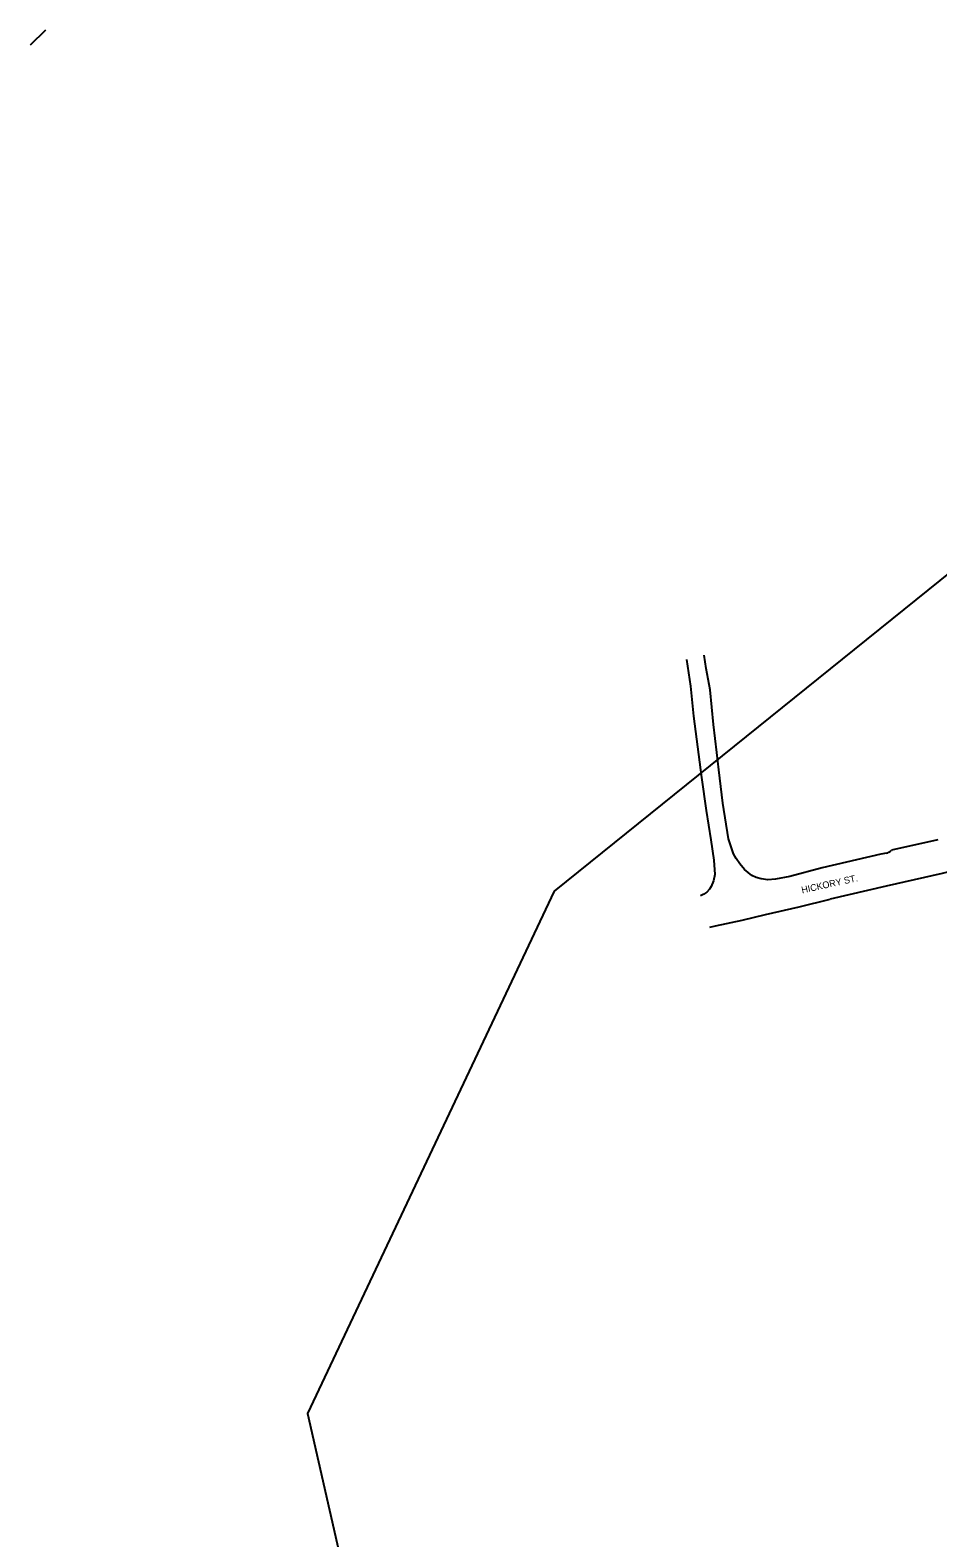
# Model space of a CAD drawing. Extents: x 553958 to 562499, y 493978 to 516388.
# Drawn here: x 556735 to 557275, y 506244 to 507140 of the extents above; entities that cross this region are included whole.
import ezdxf

# ---------------------------------------------------------------- set-up
doc = ezdxf.new("R2010")
doc.units = 0
for name, color, linetype in [('Prop Erosion Rip Rap Class II Label', 7, 'Continuous'), ('Prop Superelevation Label', 7, 'Continuous'), ('Scratch_Level_0', 7, 'Continuous'), ('Sheet Plot Border Inside CELL', 7, 'Continuous')]:
    doc.layers.add(name, color=color, linetype=linetype)

msp = doc.modelspace()

# ---------------------------------------------------------------- linework, layer by layer
at = {"layer": 'Prop Erosion Rip Rap Class II Label'}
msp.add_lwpolyline([(557510.24, 505740.54), (557854.59, 506431.05), (557889.73, 506539.36), (557425.46, 506933.59), (557046.6, 506628.46), (556899.98, 506318.25), (557006.57, 505850.3)], close=True, dxfattribs=at)
at = {"layer": 'Scratch_Level_0'}
for p, q in [((557274.6, 506658.9), (557246.99, 506652.72)), ((557246.99, 506652.72), (557246.78, 506652.5))]:
    msp.add_line(p, q, dxfattribs=at)
for points in [[(557125.25, 506766.07), (557127.58, 506750.13), (557129.42, 506732.41), (557131.76, 506714.2), (557134.17, 506695.97), (557136.94, 506676.35), (557139.77, 506658.92), (557141.53, 506646.93), (557142.04, 506638.4), (557141.31, 506634.55), (557139.95, 506631.32), (557138.83, 506629.71), (557137.27, 506627.94), (557135.58, 506626.66), (557133.46, 506625.72)], [(557205.94, 506642.27), (557186.61, 506637.13), (557178.18, 506635.58), (557173.53, 506635.12), (557169.54, 506635.72), (557166.7, 506636.64), (557164.13, 506637.82), (557161.89, 506639.51), (557159.79, 506641.38), (557157, 506644.63), (557154.74, 506647.84), (557153.25, 506650.68), (557150.25, 506659.52), (557146.74, 506680.8), (557144.48, 506700.55), (557143.29, 506710.73), (557141.31, 506727.51), (557139.32, 506748.07), (557136.95, 506760.7), (557135.8, 506768.68)], [(557425.41, 506672.82), (557425.31, 506672.8), (557414.94, 506670.36), (557382.4, 506663.12), (557348.32, 506655.29), (557313.04, 506647.26), (557294.81, 506643.23), (557291.75, 506642.48), (557277.09, 506639.04), (557243.83, 506631.4), (557210.53, 506623.68)], [(557244.12, 506651.09), (557240.65, 506650.36), (557205.94, 506642.27)], [(557139.19, 506607.12), (557142.41, 506607.91), (557158.24, 506611.16), (557172.11, 506614.58), (557192.17, 506619.24), (557210.53, 506623.68)]]:
    msp.add_lwpolyline(points, dxfattribs=at)
msp.add_ellipse((557242.82, 506656.77), major_axis=(1.93, -5.49), ratio=0.999787, start_param=6.170286, end_param=6.692531, dxfattribs=at)
at = {"layer": 'Sheet Plot Border Inside CELL'}
msp.add_line((556744.27, 507139.78), (556735.19, 507130.87), dxfattribs=at)

# ---------------------------------------------------------------- texts
at = {"layer": 'Prop Superelevation Label'}
msp.add_text('HICKORY ST.     ', height=4, rotation=12.45591, dxfattribs=at).set_placement((557193.98, 506627.07))

doc.saveas('drawing.dxf')
